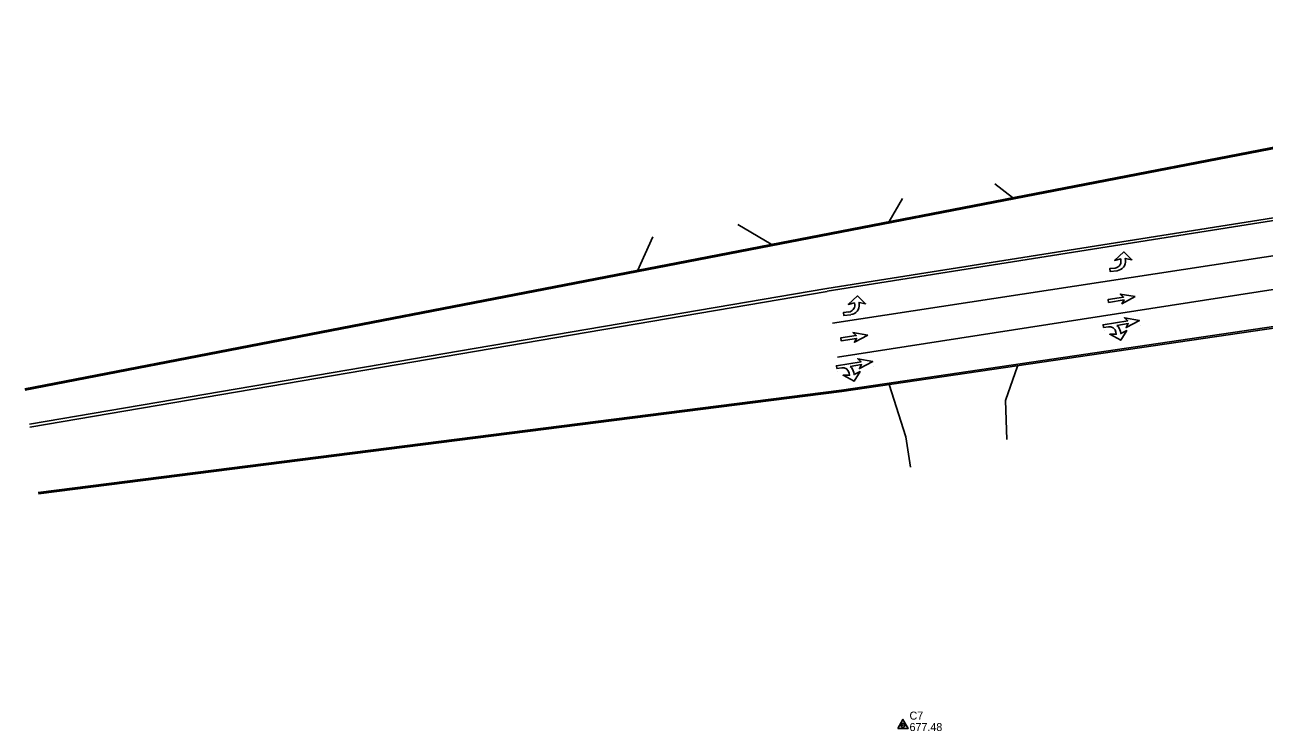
# Model space of a CAD drawing. Extents: x 2129547 to 2134906, y 657330 to 659734.
# Drawn here: x 2131588.8 to 2132022.3, y 657381.5 to 657628.3 of the extents above; entities that cross this region are included whole.
import ezdxf

# ---------------------------------------------------------------- set-up
doc = ezdxf.new("R2010")
doc.units = 0
for name, color, linetype in [('Default', 7, 'Continuous'), ('PM_X_Arrows2', 7, 'Continuous'), ('PM_X_Cells', 7, 'Continuous'), ('PM_X_Channelizing_Line2', 7, 'Continuous'), ('PM_X_CL_Double_Solid2', 7, 'Continuous'), ('PM_X_Lane_Line2', 7, 'Continuous'), ('PV_X_Curb', 7, 'Continuous'), ('PV_X_CURB2', 7, 'Continuous'), ('PV_X_EOP', 7, 'Continuous'), ('PV_X_EOP2', 7, 'Continuous'), ('SV_P_Aerial_Targets', 7, 'Continuous')]:
    doc.layers.add(name, color=color, linetype=linetype)

# ---------------------------------------------------------------- blocks, each defined once
blk = doc.blocks.new('FCTRL')
at = {"layer": 'SV_P_Aerial_Targets'}
blk.add_lwpolyline([(-0.0229, -0.0147), (0.0229, -0.0147), (0, 0.0262)], close=True, dxfattribs=at)
for radius in [0.00889, 0.00203]:
    blk.add_circle((0, 0), radius, dxfattribs=at)
blk = doc.blocks.new('PMLFT')
at = {"layer": 'PM_X_Cells'}
for points in [[(-0.57, 0), (-0.57, 0), (-0.57, 0.17), (0, 0), (-0.65, 0.76), (-1.54, 0.08), (-0.98, 0.17), (-0.98, -0.01)], [(-1.56, -0.59), (-2.03, -0.59), (-2.03, -0.85), (-1.4, -0.85)]]:
    blk.add_lwpolyline(points, dxfattribs=at)
for centre, radius, end in [((-1.56, -0.01), 0.583, 0), ((-1.4, -0.01), 0.833, 0.9085)]:
    blk.add_arc(centre, radius, 270, end, dxfattribs=at)
blk = doc.blocks.new('PMTHR')
at = {"layer": 'PM_X_Cells'}
blk.add_lwpolyline([(0, 0), (-1.27, -0.44), (-1.02, -0.13), (-2.41, -0.13), (-2.41, 0.13), (-1.02, 0.13), (-1.27, 0.44)], close=True, dxfattribs=at)
blk = doc.blocks.new('POINT_DISPLAY')
at = {"layer": 'Default'}
blk.add_line((0, 0), (0, 0), dxfattribs=at)
blk = doc.blocks.new('PMTR')
at = {"layer": 'Default'}
for points in [[(-3.24, 0.3), (-3.24, 0.55), (-1.02, 0.55), (-1.27, 0.86), (0, 0.42), (-1.27, -0.02), (-1.02, 0.3), (-2.06, 0.3)], [(-2.81, 0.3), (-2.81, 0.3), (-3.24, 0.3)], [(-1.82, -0.3), (-1.82, -0.3), (-1.82, -0.47), (-1.25, -0.3), (-1.91, -1.06), (-2.8, -0.38), (-2.23, -0.47), (-2.23, -0.29)]]:
    blk.add_lwpolyline(points, dxfattribs=at)
for centre, radius, start, end in [((-2.81, -0.29), 0.583, 0, 90), ((-2.66, -0.28), 0.833, 359.0915, 44.0466)]:
    blk.add_arc(centre, radius, start, end, dxfattribs=at)
for p in [(-3.24, 0), (0, 0)]:
    blk.add_blockref('POINT_DISPLAY', p, dxfattribs=at)

msp = doc.modelspace()

# ---------------------------------------------------------------- linework, layer by layer
at = {"layer": 'PM_X_Channelizing_Line2'}
msp.add_line((2132377.13, 657601.48), (2131871.23, 657524.02), dxfattribs=at)
at = {"layer": 'PM_X_CL_Double_Solid2'}
for p, q in [((2132036.42, 657562.61), (2131869.26, 657536.12)), ((2131869.4, 657535.2), (2132036.51, 657561.65)), ((2131869.26, 657536.12), (2131590.39, 657488.7)), ((2131869.42, 657535.13), (2131590.56, 657487.71))]:
    msp.add_line(p, q, dxfattribs=at)
at = {"layer": 'PM_X_Lane_Line2'}
msp.add_line((2132041.07, 657538.3), (2131873, 657512.16), dxfattribs=at)
at = {"layer": 'PV_X_Curb'}
msp.add_lwpolyline([(2131593.52, 657464.36), (2131874.49, 657500.16), (2132044.59, 657525.14)], dxfattribs=at)
at = {"layer": 'PV_X_CURB2'}
msp.add_lwpolyline([(2131588.77, 657501.11), (2132034.75, 657587.32), (2132293.63, 657628.3)], dxfattribs=at)
at = {"layer": 'PV_X_EOP'}
for p, q in [((2131934.2, 657567.95), (2131928.07, 657572.73)), ((2131895.71, 657567.63), (2131891.08, 657559.57)), ((2131838.11, 657558.56), (2131849.8, 657551.68)), ((2131808.44, 657554.22), (2131803.05, 657542.39)), ((2131935.93, 657509.04), (2131931.76, 657496.98)), ((2131891.08, 657502.64), (2131896.89, 657484.33)), ((2131931.76, 657496.98), (2131932.2, 657483.44)), ((2131896.89, 657484.33), (2131898.53, 657473.76))]:
    msp.add_line(p, q, dxfattribs=at)
msp.add_lwpolyline([(2131593.45, 657464.86), (2131874.42, 657500.65), (2132044.51, 657525.63)], dxfattribs=at)
at = {"layer": 'PV_X_EOP2'}
msp.add_lwpolyline([(2131588.86, 657500.62), (2132034.83, 657586.83), (2132293.71, 657627.81)], dxfattribs=at)

# ---------------------------------------------------------------- block references
at = {"layer": 'PM_X_Arrows2'}
for name, p, xscale, yscale, rotation in [('PMLFT', (2131975.97, 657546.21), 3.9370000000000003, 3.9370000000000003, 5.39626147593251), ('PMLFT', (2131882.86, 657530.85), 3.9370000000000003, 3.9370000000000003, 5.39626147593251), ('PMTHR', (2131977.13, 657533.31), 3.9370000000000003, 3.9370000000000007, 8.96748852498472), ('PMTR', (2131978.86, 657523.4), 3.937, 3.937000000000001, 9.214110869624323), ('PMTHR', (2131883.59, 657519.85), 3.9370000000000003, 3.9370000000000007, 8.967488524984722), ('PMTR', (2131885.59, 657509.08), 3.937, 3.937000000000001, 9.214110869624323)]:
    msp.add_blockref(name, p, dxfattribs=dict(at, xscale=xscale, yscale=yscale, rotation=rotation))
at = {"layer": 'SV_P_Aerial_Targets', "xscale": 78.74000000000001, "yscale": 78.74000000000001}
msp.add_blockref('FCTRL', (2131895.88, 657383.52), dxfattribs=at)

# ---------------------------------------------------------------- texts
at = {"layer": 'SV_P_Aerial_Targets'}
for s, p in [('C7', (2131898.2, 657385.52)), ('677.48', (2131898.2, 657381.52))]:
    msp.add_text(s, height=2.8, dxfattribs=at).set_placement(p)

doc.saveas('drawing.dxf')
